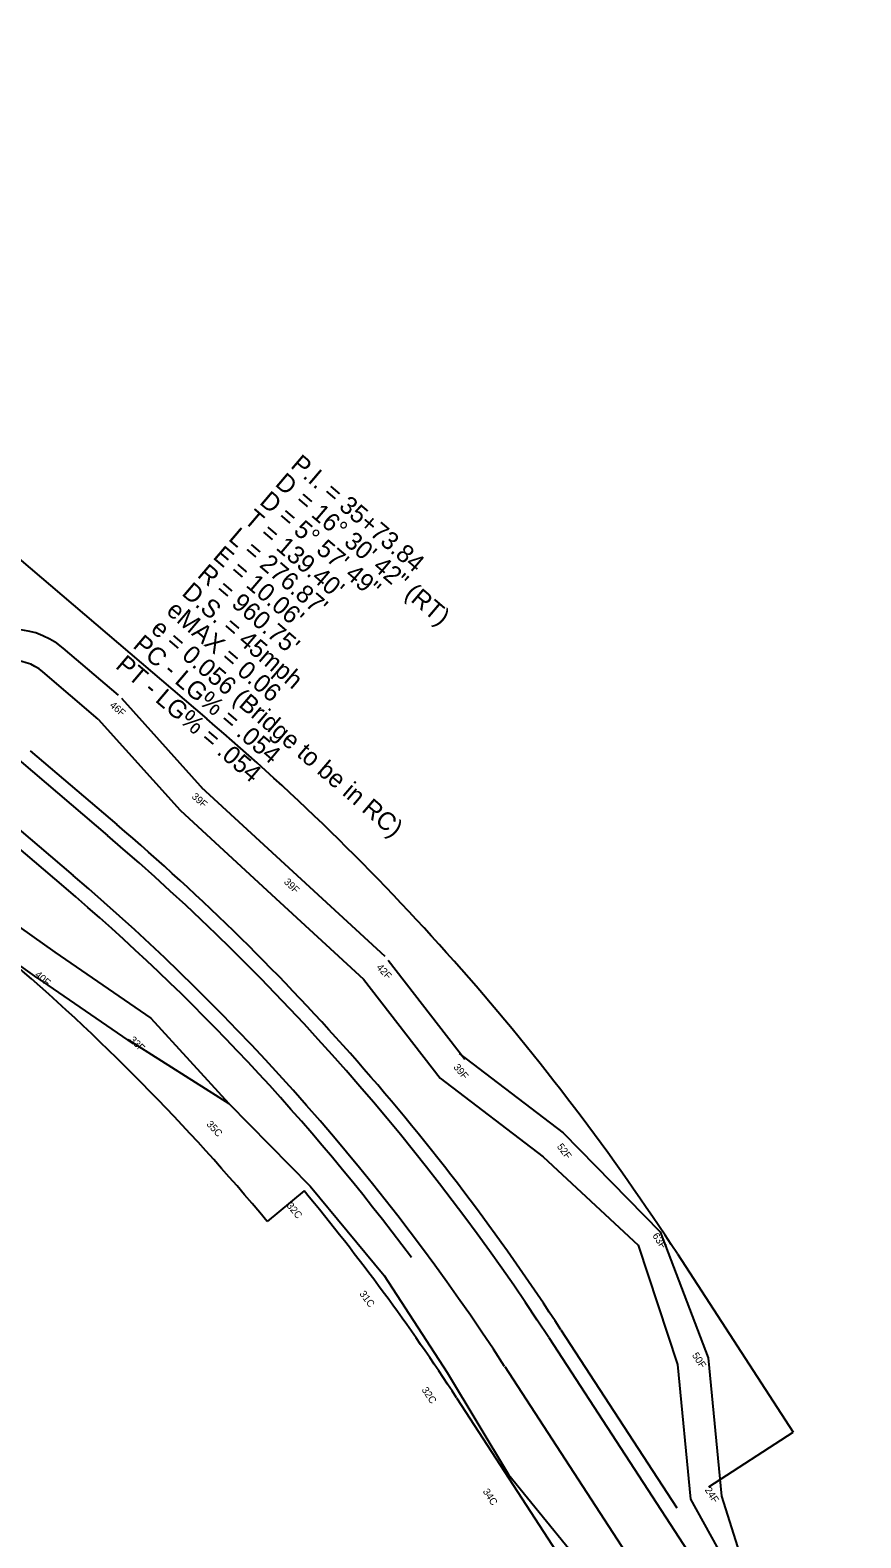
# Model space of a CAD drawing. Extents: x 2006539 to 2009039, y 1001971 to 1004377.
# Drawn here: x 2007969 to 2008316, y 1002537 to 1003166 of the extents above; entities that cross this region are included whole.
import ezdxf

# ---------------------------------------------------------------- set-up
doc = ezdxf.new("R2010")
doc.units = 0
for name, color, linetype in [('BR_PROPOSED_TRAVELWAY', 7, 'Continuous'), ('RD_PD_CstnLmt', 7, 'Continuous'), ('RD_PD_CstnLmt_TX', 7, 'Continuous'), ('RD_PD_DR_ErosCtrl', 7, 'Continuous'), ('RD_PD_Final_TrvlWay', 7, 'Continuous'), ('RD_PD_GR', 7, 'Continuous'), ('RD_PD_RW', 7, 'Continuous')]:
    doc.layers.add(name, color=color, linetype=linetype)

msp = doc.modelspace()

# ---------------------------------------------------------------- linework, layer by layer
at = {"layer": 'RD_PD_CstnLmt'}
for p, q in [((2007997.68, 1002878.77), (2007974.61, 1002898.42)), ((2007997.68, 1002878.77), (2008031.81, 1002840.77)), ((2008031.81, 1002840.77), (2008070.04, 1002805.49)), ((2007939.15, 1002810.07), (2007979.54, 1002781.39)), ((2008070.04, 1002805.49), (2008108.43, 1002770.15)), ((2007979.54, 1002781.39), (2008019.57, 1002753.84)), ((2008108.43, 1002770.15), (2008140.37, 1002728.87)), ((2008019.57, 1002753.84), (2008052.19, 1002718.28)), ((2008140.37, 1002728.87), (2008183.34, 1002696.06)), ((2008052.19, 1002718.28), (2008086.11, 1002683.83)), ((2008183.34, 1002696.06), (2008223.01, 1002659.19)), ((2008086.11, 1002683.83), (2008116.95, 1002646.54)), ((2008223.01, 1002659.19), (2008239.5, 1002609.37)), ((2008116.95, 1002646.54), (2008143.32, 1002605.97)), ((2008239.5, 1002609.37), (2008244.81, 1002553.17)), ((2008143.32, 1002605.97), (2008168.94, 1002563.44)), ((2008168.94, 1002563.44), (2008200.66, 1002524.43)), ((2008244.81, 1002553.17), (2008269.08, 1002509.31))]:
    msp.add_line(p, q, dxfattribs=at)
msp.add_arc((2007961.64, 1002883.2), 20, 49.57273, 139.57273, dxfattribs=at)
at = {"layer": 'RD_PD_DR_ErosCtrl'}
for p, q in [((2008006.11, 1002888.67), (2007983.04, 1002908.32)), ((2008007.35, 1002887.46), (2008041.48, 1002849.45)), ((2008040.63, 1002850.32), (2008078.86, 1002815.05)), ((2008078.85, 1002815.06), (2008117.24, 1002779.71)), ((2007931.63, 1002799.47), (2007972.01, 1002770.79)), ((2008118.71, 1002778.1), (2008150.65, 1002736.82)), ((2007972.17, 1002770.68), (2008012.2, 1002743.13)), ((2008009.99, 1002745.05), (2008052.19, 1002718.28)), ((2008148.25, 1002739.2), (2008191.73, 1002706.01)), ((2008191.73, 1002706.01), (2008232.21, 1002664.68)), ((2008232.21, 1002664.68), (2008252.3, 1002612.06)), ((2008252.3, 1002612.06), (2008257.75, 1002554.39)), ((2008257.75, 1002554.39), (2008271.7, 1002510.76))]:
    msp.add_line(p, q, dxfattribs=at)
msp.add_arc((2007961.64, 1002883.2), 33, 49.57273, 139.57273, dxfattribs=at)
at = {"layer": 'RD_PD_Final_TrvlWay'}
for p, q in [((2007566.9, 1003200.38), (2008001.5, 1002830.16)), ((2007552.64, 1003183.64), (2007987.23, 1002813.41)), ((2008185.75, 1002620.55), (2008315.96, 1002420.51)), ((2008167.31, 1002608.55), (2008297.53, 1002408.5))]:
    msp.add_line(p, q, dxfattribs=at)
for radius in [971.75, 949.75]:
    msp.add_arc((2007371.33, 1002090.43), radius, 33.06116, 49.57273, dxfattribs=at)
at = {"layer": 'RD_PD_GR'}
for p, q in [((2007969.28, 1002865.48), (2008005.39, 1002834.72)), ((2007983.34, 1002808.84), (2007947.23, 1002839.6)), ((2008190.78, 1002623.83), (2008239.16, 1002549.49))]:
    msp.add_line(p, q, dxfattribs=at)
for radius, start in [(977.75, 33.06116), (943.75, 36.66204)]:
    msp.add_arc((2007371.33, 1002090.43), radius, start, 49.57273, dxfattribs=at)
at = {"layer": 'RD_PD_RW'}
for p, q in [((2007671.19, 1003195.62), (2008043, 1002878.88)), ((2008083.62, 1002681.76), (2008068.23, 1002668.98)), ((2008239.39, 1002655.47), (2008287.77, 1002581.13)), ((2008147.2, 1002595.46), (2008277.41, 1002395.41)), ((2008252.57, 1002558.22), (2008287.77, 1002581.13))]:
    msp.add_line(p, q, dxfattribs=at)
for radius, start, end in [(1035.75, 33.06116, 49.57273), (905.75, 39.69899, 49.57273), (925.75, 33.06116, 39.69899)]:
    msp.add_arc((2007371.33, 1002090.43), radius, start, end, dxfattribs=at)

# ---------------------------------------------------------------- texts
at = {"layer": 'BR_PROPOSED_TRAVELWAY'}
for s, rotation, p in [('P.I. = 35+73.84', 319.55578, (2008077.56, 1002984.04)), ('D', 319.55578, (2008071.07, 1002976.43)), ('D = 5%%d 57\' 49"', 319.55578, (2008064.59, 1002968.82)), ('    = 16%%d 30\' 42" (RT)', 319.55578, (2008071.07, 1002976.43)), ("T = 139.40'", 319.55578, (2008058.1, 1002961.21)), ("L = 276.87'", 319.55578, (2008051.61, 1002953.6)), ("E = 10.06'", 319.55578, (2008045.13, 1002945.99)), ("R = 960.75'", 319.55578, (2008038.64, 1002938.38)), ('D.S. = 45mph', 319.55578, (2008032.15, 1002930.77)), ('eMAX = 0.06', 319.55578, (2008025.66, 1002923.15)), ('e = 0.056 (Bridge to be in RC)', 319.55578, (2008019.18, 1002915.54)), ('PC - LG% = .054', 319.64726, (2008011.75, 1002908.86)), ('PT - LG% = .054', 319.64726, (2008004.51, 1002900.36))]:
    msp.add_text(s, height=7.5, rotation=rotation, dxfattribs=at).set_placement(p)
at = {"layer": 'RD_PD_CstnLmt_TX'}
for s, rotation, p in [('46F', 319.57273, (2008002.22, 1002884.1)), ('39F', 318.64442, (2008036.44, 1002846.02)), ('39F', 315.66261, (2008074.94, 1002810.5)), ('40F', 318.64442, (2007970.95, 1002771.63)), ('42F', 312.6808, (2008113.58, 1002774.89)), ('33F', 315.66261, (2008010.49, 1002744.54)), ('39F', 309.69899, (2008145.75, 1002733.34)), ('35C', 312.6808, (2008042.63, 1002709.47)), ('52F', 306.71718, (2008188.96, 1002700.25)), ('32C', 309.69899, (2008076.11, 1002675.52)), ('63F', 303.73537, (2008228.83, 1002663.08)), ('31C', 306.71718, (2008106.53, 1002638.77)), ('50F', 303.06116, (2008245.37, 1002613.19)), ('32C', 303.73537, (2008132.51, 1002598.75)), ('34C', 303.06116, (2008158.04, 1002556.35)), ('24F', 303.06116, (2008250.68, 1002556.99))]:
    msp.add_text(s, height=3, rotation=rotation, dxfattribs=at).set_placement(p)

doc.saveas('drawing.dxf')
